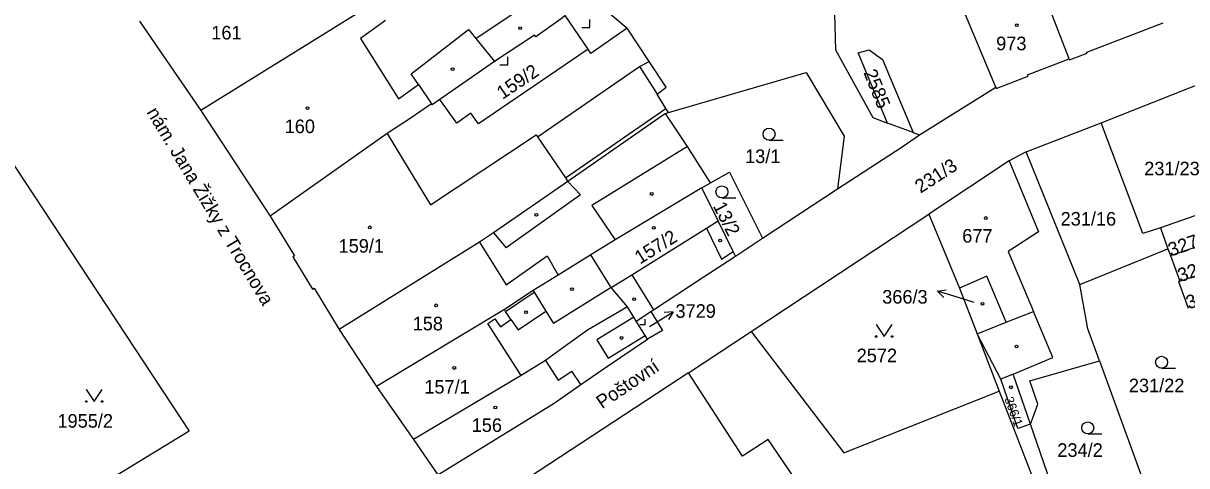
# Model space of a CAD drawing. Extents: x -679220 to -673243, y -1075091 to -1066557.
# Drawn here: x -676327.7 to -676182, y -1071676.2 to -1071620.8 of the extents above; entities that cross this region are included whole.
import ezdxf

# ---------------------------------------------------------------- set-up
doc = ezdxf.new("R2010")
doc.units = 0
for name, color, linetype in [('Hranice parcel', 7, 'Continuous'), ('Parcelní čísla', 7, 'Continuous'), ('Pop  PČ popisy', 7, 'Continuous'), ('Vnitřní kresba', 7, 'Continuous'), ('Značky budov', 7, 'Continuous'), ('Značky kultur', 7, 'Continuous')]:
    doc.layers.add(name, color=color, linetype=linetype)

msp = doc.modelspace()

# ---------------------------------------------------------------- linework, layer by layer
at = {"layer": 'Hranice parcel'}
for p, q in [((-676256.93, -1071624.07), (-676259.79, -1071619.88)), ((-676313.09, -1071620.56), (-676305.44, -1071631.74)), ((-676215.43, -1071634.8), (-676205.88, -1071628.82)), ((-676192.67, -1071633.32), (-676179.39, -1071628.06)), ((-676305.44, -1071631.74), (-676296.73, -1071644.97)), ((-676247.22, -1071632.12), (-676246.86, -1071632.02)), ((-676216.21, -1071634.52), (-676219.43, -1071633.33)), ((-676202.07, -1071636.95), (-676192.67, -1071633.32)), ((-676216.21, -1071634.52), (-676215.43, -1071634.8)), ((-676195.37, -1071653.55), (-676202.07, -1071636.95)), ((-676242.69, -1071641.44), (-676241.62, -1071640.83)), ((-676235.09, -1071647.75), (-676225.72, -1071641.56)), ((-676236.52, -1071659.42), (-676214.28, -1071644.72)), ((-676214.28, -1071644.72), (-676210.42, -1071654.02)), ((-676179.16, -1071644.33), (-676185.27, -1071646.43)), ((-676185.27, -1071646.43), (-676184.32, -1071649.06)), ((-676238.49, -1071650), (-676235.09, -1071647.75)), ((-676184, -1071649.93), (-676177.86, -1071647.82)), ((-676195.37, -1071653.55), (-676184.32, -1071649.06)), ((-676184.32, -1071649.06), (-676184, -1071649.93)), ((-676184, -1071649.93), (-676182.84, -1071653.13)), ((-676182.84, -1071653.13), (-676176.67, -1071651.01)), ((-676210.42, -1071654.02), (-676208.21, -1071659.74)), ((-676250.9, -1071658.13), (-676249.09, -1071656.93)), ((-676288.1, -1071659.17), (-676283.43, -1071666.32)), ((-676244.34, -1071664.59), (-676236.52, -1071659.42)), ((-676208.21, -1071659.74), (-676205.45, -1071666.89)), ((-676244.34, -1071664.59), (-676267.58, -1071679.82)), ((-676283.43, -1071666.32), (-676278.79, -1071672.97)), ((-676205.45, -1071666.89), (-676199.16, -1071683.19)), ((-676197.47, -1071682.78), (-676201.55, -1071671.02)), ((-676278.79, -1071672.97), (-676275.74, -1071677.38))]:
    msp.add_line(p, q, dxfattribs=at)
for points in [[(-676254.27, -1071592.33), (-676250.44, -1071598.38), (-676250.16, -1071598.2), (-676242.88, -1071609.41), (-676233.68, -1071603.54), (-676226.09, -1071619.69), (-676225.97, -1071624.14), (-676221.28, -1071632.65), (-676219.43, -1071633.33)], [(-676196.67, -1071625.28), (-676200.44, -1071615.54), (-676201.03, -1071614.01), (-676202.2, -1071610.84), (-676203.22, -1071608.14), (-676204.4, -1071605.31)], [(-676205.88, -1071628.82), (-676209.9, -1071619.28), (-676212.5, -1071613.48), (-676214.24, -1071609.44)], [(-676272.57, -1071610.82), (-676276.28, -1071613.95), (-676279.35, -1071615.75), (-676283.81, -1071618.35), (-676305.44, -1071631.74)], [(-676256.92, -1071617.84), (-676256.44, -1071617.49), (-676256.07, -1071618.02), (-676252.04, -1071621.43)], [(-676259.79, -1071619.88), (-676260.14, -1071620.14), (-676263.49, -1071622.54), (-676263.63, -1071622.34), (-676268.66, -1071625.61), (-676275.49, -1071630.36)], [(-676252.04, -1071621.43), (-676256.57, -1071624.61), (-676256.93, -1071624.07)], [(-676246.86, -1071632.02), (-676247.18, -1071631.5), (-676248.3, -1071629.73), (-676247.17, -1071628.82), (-676249.29, -1071625.6), (-676252.04, -1071621.43)], [(-676196.67, -1071625.28), (-676196.63, -1071625.4), (-676194.45, -1071624.56), (-676194.49, -1071624.45), (-676184.92, -1071620.78)], [(-676256.93, -1071624.07), (-676270.67, -1071633.41), (-676271.6, -1071632.09), (-676273.39, -1071633.33), (-676275.49, -1071630.36)], [(-676219.43, -1071633.33), (-676223.1, -1071624.53), (-676221.72, -1071624.15), (-676220.07, -1071625.35), (-676216.21, -1071634.52)], [(-676205.88, -1071628.82), (-676205.82, -1071628.99), (-676201.84, -1071627.46), (-676201.9, -1071627.29), (-676196.67, -1071625.28)], [(-676246.86, -1071632.02), (-676229.61, -1071626.99), (-676224.86, -1071634.98), (-676225.72, -1071641.56)], [(-676275.49, -1071630.36), (-676276.45, -1071631.03), (-676276.53, -1071630.92), (-676279.21, -1071632.74), (-676282.09, -1071634.64), (-676296.73, -1071644.97)], [(-676247.22, -1071632.12), (-676259.45, -1071640.64), (-676268.78, -1071647.06), (-676270.54, -1071648.26), (-676288.1, -1071659.17)], [(-676241.62, -1071640.83), (-676244.47, -1071636.28), (-676247.22, -1071632.12)], [(-676185.27, -1071646.43), (-676187.48, -1071647.18), (-676192.67, -1071633.32)], [(-676225.72, -1071641.56), (-676217.6, -1071636.32), (-676215.43, -1071634.8)], [(-676202.07, -1071636.95), (-676204.21, -1071638.05), (-676214.28, -1071644.72)], [(-676241.62, -1071640.83), (-676239.22, -1071639.46), (-676235.09, -1071647.75)], [(-676242.69, -1071641.44), (-676253.54, -1071647.95), (-676256.61, -1071649.82)], [(-676238.49, -1071650), (-676238.77, -1071649.43), (-676240.63, -1071645.59), (-676242.69, -1071641.44)], [(-676296.73, -1071644.97), (-676293.69, -1071649.96), (-676293.9, -1071650.09), (-676291.44, -1071654.13), (-676291.24, -1071654.01), (-676288.1, -1071659.17)], [(-676256.61, -1071649.82), (-676260.69, -1071652.36), (-676263.83, -1071654.31), (-676267.42, -1071656.68), (-676283.43, -1071666.32)], [(-676252, -1071656.35), (-676254.05, -1071653.94), (-676256.61, -1071649.82)], [(-676249.09, -1071656.93), (-676248.74, -1071656.71), (-676242.52, -1071652.62), (-676238.49, -1071650)], [(-676208.21, -1071659.74), (-676204.56, -1071658.27), (-676206.98, -1071652.49), (-676210.42, -1071654.02)], [(-676192.9, -1071663.12), (-676194.37, -1071659.08), (-676195.37, -1071653.55)], [(-676182.84, -1071653.13), (-676182.98, -1071653.18), (-676181.78, -1071656.49)], [(-676252, -1071656.35), (-676256.99, -1071659.28), (-676259.51, -1071661.04), (-676262.28, -1071663.06), (-676265.3, -1071664.96), (-676278.79, -1071672.97)], [(-676250.9, -1071658.13), (-676251.22, -1071657.62), (-676252, -1071656.35)], [(-676249.51, -1071660.4), (-676249.8, -1071659.93), (-676250.9, -1071658.13)], [(-676249.09, -1071656.93), (-676247.6, -1071659.3), (-676249.51, -1071660.4)], [(-676236.52, -1071659.42), (-676224.9, -1071674.63), (-676205.45, -1071666.89)], [(-676201.55, -1071671.02), (-676203.72, -1071664.79), (-676205.23, -1071665.42), (-676208.21, -1071659.74)], [(-676275.74, -1071677.38), (-676261.19, -1071668.4), (-676257.85, -1071666.06), (-676254.49, -1071663.79), (-676249.51, -1071660.4)], [(-676201.55, -1071671.02), (-676200.62, -1071668.53), (-676201.63, -1071665.6), (-676192.9, -1071663.12)], [(-676192.9, -1071663.12), (-676187.41, -1071678.15), (-676186.72, -1071680.18)], [(-676229.7, -1071705.35), (-676243, -1071685.11), (-676231.35, -1071677.42), (-676234.39, -1071672.97), (-676237.6, -1071675.04), (-676244.34, -1071664.59)]]:
    msp.add_lwpolyline(points, dxfattribs=at)
at = {"layer": 'Pop  PČ popisy'}
for p, q in [((-676213.18, -1071654.39), (-676212.08, -1071654.21)), ((-676210.31, -1071655.27), (-676213.18, -1071654.39)), ((-676213.18, -1071654.39), (-676212.37, -1071655.16)), ((-676208.57, -1071655.8), (-676210.31, -1071655.27)), ((-676248.83, -1071658.55), (-676246.29, -1071656.96)), ((-676246.29, -1071656.96), (-676247.4, -1071657.07)), ((-676246.29, -1071656.96), (-676246.87, -1071657.92)), ((-676249.25, -1071658.81), (-676248.83, -1071658.55))]:
    msp.add_line(p, q, dxfattribs=at)
at = {"layer": 'Vnitřní kresba'}
for p, q in [((-676270.98, -1071622.76), (-676262.29, -1071616.9)), ((-676282.31, -1071620.5), (-676285.45, -1071622.72)), ((-676279.08, -1071627.16), (-676271.92, -1071621.6)), ((-676271.92, -1071621.6), (-676270.98, -1071622.76)), ((-676285.45, -1071622.72), (-676280.66, -1071630.28)), ((-676270.98, -1071622.76), (-676268.66, -1071625.61)), ((-676337.64, -1071625.28), (-676306.9, -1071671.93)), ((-676263.25, -1071635.07), (-676250.49, -1071626.26)), ((-676250.49, -1071626.26), (-676249.29, -1071625.6)), ((-676250.49, -1071626.26), (-676248.3, -1071629.73)), ((-676278.18, -1071628.48), (-676279.08, -1071627.16)), ((-676280.66, -1071630.28), (-676278.18, -1071628.48)), ((-676278.18, -1071628.48), (-676276.53, -1071630.92)), ((-676259.76, -1071640.19), (-676247.18, -1071631.5)), ((-676282.09, -1071634.64), (-676279.35, -1071639.2)), ((-676276.65, -1071643.59), (-676263.42, -1071634.82)), ((-676263.42, -1071634.82), (-676263.25, -1071635.07)), ((-676263.25, -1071635.07), (-676259.76, -1071640.19)), ((-676244.47, -1071636.28), (-676256.46, -1071643.66)), ((-676279.35, -1071639.2), (-676276.65, -1071643.59)), ((-676204.21, -1071638.05), (-676200.54, -1071646.93)), ((-676259.76, -1071640.19), (-676259.45, -1071640.64)), ((-676259.45, -1071640.64), (-676257.88, -1071642.31)), ((-676257.88, -1071642.31), (-676267.19, -1071648.94)), ((-676256.46, -1071643.66), (-676253.54, -1071647.95)), ((-676251.45, -1071652.32), (-676242.11, -1071646.51)), ((-676242.11, -1071646.51), (-676240.63, -1071645.59)), ((-676242.11, -1071646.51), (-676240.23, -1071650.38)), ((-676268.78, -1071647.06), (-676267.19, -1071648.94)), ((-676200.54, -1071646.93), (-676204.31, -1071649.42)), ((-676270.54, -1071648.26), (-676267.19, -1071653.57)), ((-676240.23, -1071650.38), (-676238.77, -1071649.43)), ((-676204.31, -1071649.42), (-676201.16, -1071656.91)), ((-676267.19, -1071653.57), (-676262.06, -1071649.96)), ((-676262.06, -1071649.96), (-676260.69, -1071652.36)), ((-676254.05, -1071653.94), (-676251.45, -1071652.32)), ((-676251.45, -1071652.32), (-676248.74, -1071656.71)), ((-676254.05, -1071653.94), (-676261.27, -1071658.43)), ((-676267.26, -1071656.93), (-676263.7, -1071654.52)), ((-676263.83, -1071654.31), (-676263.7, -1071654.52)), ((-676263.7, -1071654.52), (-676262.22, -1071656.9)), ((-676267.26, -1071656.93), (-676267.42, -1071656.68)), ((-676269.5, -1071658.42), (-676268.61, -1071657.86)), ((-676268.61, -1071657.86), (-676267.92, -1071658.83)), ((-676267.92, -1071658.83), (-676266.62, -1071657.91)), ((-676266.62, -1071657.91), (-676267.26, -1071656.93)), ((-676266.62, -1071657.91), (-676265.69, -1071659.22)), ((-676265.69, -1071659.22), (-676262.22, -1071656.9)), ((-676262.22, -1071656.9), (-676261.27, -1071658.43)), ((-676251.22, -1071657.62), (-676255.84, -1071660.46)), ((-676204.56, -1071658.27), (-676201.16, -1071656.91)), ((-676198.74, -1071662.7), (-676201.16, -1071656.91)), ((-676265.3, -1071664.96), (-676269.5, -1071658.42)), ((-676255.84, -1071660.46), (-676254.42, -1071662.77)), ((-676254.42, -1071662.77), (-676249.8, -1071659.93)), ((-676262.28, -1071663.06), (-676260.69, -1071665.52)), ((-676203.72, -1071664.79), (-676198.74, -1071662.7)), ((-676260.69, -1071665.52), (-676258.97, -1071664.41)), ((-676257.85, -1071666.06), (-676258.97, -1071664.41)), ((-676203.1, -1071671.56), (-676205.23, -1071665.42)), ((-676201.55, -1071671.02), (-676203.1, -1071671.56)), ((-676306.9, -1071671.93), (-676348.68, -1071697.31))]:
    msp.add_line(p, q, dxfattribs=at)
at = {"layer": 'Značky budov'}
for centre in [(-676265.43, -1071621.45), (-676203.24, -1071621.06), (-676273.9, -1071626.57), (-676292.08, -1071631.47), (-676248.97, -1071642.21), (-676263.41, -1071644.83), (-676207.12, -1071645.22), (-676284.26, -1071646.39), (-676248.71, -1071646.44), (-676240.39, -1071648.04), (-676258.95, -1071654.14), (-676251.17, -1071655.39), (-676275.95, -1071656.16), (-676264.71, -1071657.01), (-676207.54, -1071655.96), (-676252.75, -1071660.24), (-676203.29, -1071661.3), (-676273.69, -1071664), (-676203.98, -1071666.42), (-676268.55, -1071668.96)]:
    msp.add_circle(centre, 0.175, dxfattribs=at)
at = {"layer": 'Značky kultur'}
for p, q in [((-676256.71, -1071621.37), (-676256.71, -1071620.37)), ((-676257.71, -1071621.37), (-676256.71, -1071621.37)), ((-676267.97, -1071626.02), (-676266.97, -1071626.02)), ((-676266.97, -1071626.02), (-676266.97, -1071625.02)), ((-676234.27, -1071635.47), (-676232.52, -1071635.47)), ((-676240.18, -1071642.7), (-676238.43, -1071642.7)), ((-676249.78, -1071658.54), (-676249.78, -1071657.87)), ((-676250.45, -1071658.54), (-676249.78, -1071658.54)), ((-676185.11, -1071664.04), (-676183.36, -1071664.04)), ((-676194.36, -1071672.25), (-676192.61, -1071672.25))]:
    msp.add_line(p, q, dxfattribs=at)
for points in [[(-676220.86, -1071658.56), (-676219.86, -1071660.06), (-676218.86, -1071658.56)], [(-676319.78, -1071666.7), (-676318.78, -1071668.2), (-676317.78, -1071666.7)]]:
    msp.add_lwpolyline(points, dxfattribs=at)
for centre, radius in [((-676234.27, -1071634.72), 0.75), ((-676240.18, -1071641.95), 0.75), ((-676220.86, -1071660.06), 0.1), ((-676218.86, -1071660.06), 0.1), ((-676185.11, -1071663.29), 0.75), ((-676319.78, -1071668.2), 0.1), ((-676317.78, -1071668.2), 0.1), ((-676194.36, -1071671.5), 0.75)]:
    msp.add_circle(centre, radius, dxfattribs=at)

# ---------------------------------------------------------------- texts
at = {"layer": 'Parcelní čísla'}
for s, p in [('161', (-676304.12, -1071622.86)), ('973', (-676205.83, -1071624.21)), ('160', (-676294.93, -1071634.59)), ('13/1', (-676237.27, -1071638.34)), ('231/23', (-676187.29, -1071639.87)), ('231/16', (-676197.76, -1071646.17)), ('677', (-676210.08, -1071648.3)), ('159/1', (-676288.18, -1071649.56)), ('366/3', (-676220.1, -1071655.94)), ('3729', (-676245.99, -1071657.72)), ('158', (-676278.9, -1071659.29)), ('2572', (-676223.3, -1071663.28)), ('157/1', (-676277.44, -1071667.21)), ('231/22', (-676189.21, -1071667.04)), ('1955/2', (-676323.38, -1071671.48)), ('156', (-676271.51, -1071672.01)), ('234/2', (-676198.17, -1071675.13))]:
    msp.add_text(s, height=1.7, dxfattribs=at).set_placement(p)
for s, height, rotation, p in [('159/2', 1.7, 34, (-676267.65, -1071630.43)), ('2585', 1.7, 292, (-676222.48, -1071626.99)), ('231/3', 1.7, 33, (-676215.3, -1071642.18)), ('13/2', 1.7, 297, (-676241.34, -1071643.71)), ('157/2', 1.7, 32, (-676250.43, -1071651.06)), ('3272', 1.7, 19, (-676183.95, -1071650.06)), ('3273', 1.7, 19, (-676182.76, -1071653.27)), ('3274', 1.7, 19, (-676181.72, -1071656.67)), ('366/1', 1.14, 290, (-676204.82, -1071667.85))]:
    msp.add_text(s, height=height, rotation=rotation, dxfattribs=at).set_placement(p)
at = {"layer": 'Pop  PČ popisy'}
for s, rotation, p in [('nám. Jana Žižky z Trocnova', 301, (-676312.28, -1071631.97)), ('Poštovní', 34, (-676255.18, -1071669.18))]:
    msp.add_text(s, height=1.7, rotation=rotation, dxfattribs=at).set_placement(p)

doc.saveas('drawing.dxf')
